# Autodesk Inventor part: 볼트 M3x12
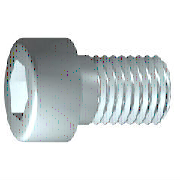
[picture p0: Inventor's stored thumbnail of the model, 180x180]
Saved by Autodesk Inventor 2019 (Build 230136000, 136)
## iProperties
IsCustomPart: 0
Created: 2012-02
Part Number: 볼트 M3x12
Material: 강철, 연강
Description: 6각머리 태핑 나사
Document SubType Name: Modeling
Standard: KS B 1003
Designer: mduedu
Standards Organization: KS
Language: ko-KR
Size Designation: M 3 x 12
Categories: <MemberInstance><Categories><Category DisplayName="조임쇠" InternalName="e4da775c-781d-43d5-af7c-5136215cf5a6" Mnemonic="FSTN"><Category DisplayName="볼트" InternalN
Density: 1 g/cm^3
Appearance: 강철
Author: mduedu
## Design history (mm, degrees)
sketch "스케치1"
  geometry: L1 (-0.867, 0)-(12, 0); L2 (12, 0)-(12, 1.5); L3 (12, 1.5)-(1.25, 1.5); L4 (1.25, 1.5)-(0.943, 1.5); L5 (0.943, 1.5)-(0, 1.5); L6 (0, 1.5)-(0, 2.75); L7 (0, 2.75)-(-3, 2.75); L8 (-3, 2.75)-(-3, 1.443); L9 (-3, 1.443)-(-1.7, 1.443); L10 (-1.7, 1.443)-(-0.867, 0); L11 (-6, 0)-(15, 0) reference; L12 (0, -0.55)-(0, 3.3) reference; L13 (1.25, 1.5)-(0, 1.5)
  constraints: 22 end point, 6 parallel, 2 collinear, 2 perpendicular, 1 horizontal, 1 point on line
  dimensions: "d1" = 10.75 distance from line of L3.end L2 (= GEL); "d2" = 0.30683 distance of L4.end L3.end (computed from GAL); "d3" = 3 distance between parallel lines of L8 L6 (= KOH); "d4" = 1.3 distance of L8.end L9.end (= INTI); "d5" = 60 deg angle of L10 L1; "d6" = 3 diameter of L3 L1 (= GD); "d7" = 3 diameter of L5 L1 (= BDM); "d8" = 2.88675 diameter of L9 L1 (= 1.1547 x SW); "d9" = 5.5 diameter of L7 L1 (= KOD); "d26" = 12 distance between parallel lines of L12 L2 (= NLG)
revolve "본체" sketch "스케치1" stored, may be unused: angle "d10" = 90 deg
sketch "스케치2"
  geometry: L1 (0, -3.85)-(0, 3.85) reference; L2 (-3.85, 0)-(3.85, 0) reference; L3 (1.443, 0)-(0.722, -1.25); L4 (0.722, -1.25)-(-0.722, -1.25); L5 (-0.722, -1.25)-(-1.443, 0); L6 (-1.443, 0)-(-0.722, 1.25); L7 (-0.722, 1.25)-(0.722, 1.25); L8 (0.722, 1.25)-(1.443, 0); 2 further points
  constraints: 12 end point, 1 coincident, 1 horizontal alignment, 1 point on line, 12 other
extrude "슬롯" join sketch "스케치2" stored distance "d11" = 10; taper "d12" = 0 deg
workplane "Work Plane1"
fillet "Fillet2" dims "d30" = 0.1 (= R)
body "Solid1"
fillet "모깎기1" dims "d17" = 0.3 (= RR)
feature "스레드" dims "d13" = 10.75 (= GEL), "d14" = 0
chamfer "모따기1" distance "d15" = 0.30673 (= -0.5 x SPD + 0.5 x GD); stored, may be unused: second distance "d16" = 0.30673 (= GUL), angle "d27" = 45 deg
other parameters: "GD" = 3 (= NND) [user parameter; used in 2 equation terms], "NLG" = 12 [user parameter; used in 1 equation term], "GEL" = 10.75 [user parameter; used in 2 equation terms], "KOD" = 5.5 [user parameter; used in 1 equation term], "KOH" = 3 [user parameter; used in 1 equation term], "INTI" = 1.3 [user parameter; used in 1 equation term], "GAL" = 0.30673 (= 0.61345 x PTC) [user parameter; used in 1 equation term], "GUL" = 0.30673 (= 0.61345 x PTC) [user parameter; used in 1 equation term], "BDM" = 3 (= NND) [user parameter; used in 1 equation term], "SW" = 2.5 [user parameter; used in 2 equation terms], "RR" = 0.3 [user parameter; used in 1 equation term], "SPD" = 2.38655 (= NND - 1.2269 x PTC) [user parameter; used in 1 equation term], "d19" = 0, "d28" = 0, "d29" = 0, "R" = 0.1 [user parameter; used in 1 equation term], "PHH" = 0.1 [user parameter], "GD1" = 2.38655 (= THREADDIA - 1.2269 x PTC) [user parameter], "THREADDIA" = 3 [user parameter; used in 1 equation term], "FAWI" = 45 deg [user parameter], "PTC" = 0.5 [user parameter; used in 5 equation terms], "NND" = 3 [user parameter; used in 3 equation terms], "TOA" = 30 deg [user parameter], "E0" = 2.8875 (= 1.155 x SW) [user parameter]
